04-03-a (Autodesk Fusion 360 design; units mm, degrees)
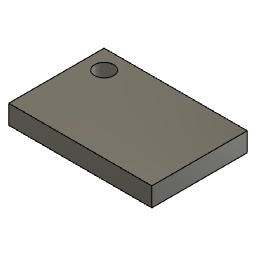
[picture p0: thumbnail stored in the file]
sketch "スケッチ" plane through (0, 0, 0) normal (0, 1, 0) x axis (1, 0, 0)
  line L1 (-15, 10) -> (15, 10)
  line L2 (-15, -10) -> (-15, 10)
  line L3 (15, -10) -> (-15, -10)
  line L4 (15, 10) -> (15, -10)
  line L5 (-15, -10) -> (15, 10)
  line L6 (15, -10) -> (-15, 10)
  point P6 (0, 0)
  point P1 (0, 0)
  point P2 (15, 10)
  point P3 (-15, 10)
  point P5 (15, -10)
  horizontal L1
  perpendicular L1 L2
  parallel L1 L3
  parallel L2 L4
  coincident L5 P6
  coincident L6 P6
  coincident P1 P6
  dimension "d5" distance P2 P3 = 30
  dimension "d6" distance P2 P5 = 20
extrude "押し出し" new body sketch "スケッチ" profile of L1 L2 L3 L4 along normal blind 4
hole "穴" HoleDepth 4 HoleDiameter 4 TipAngle 118 RefDim1 4 RefDim2 4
